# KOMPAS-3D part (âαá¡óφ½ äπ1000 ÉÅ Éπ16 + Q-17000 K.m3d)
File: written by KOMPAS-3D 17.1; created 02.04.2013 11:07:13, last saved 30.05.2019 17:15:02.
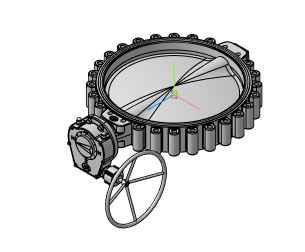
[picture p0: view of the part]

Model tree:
1. Операция без истории:4

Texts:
  PART-1-DESC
